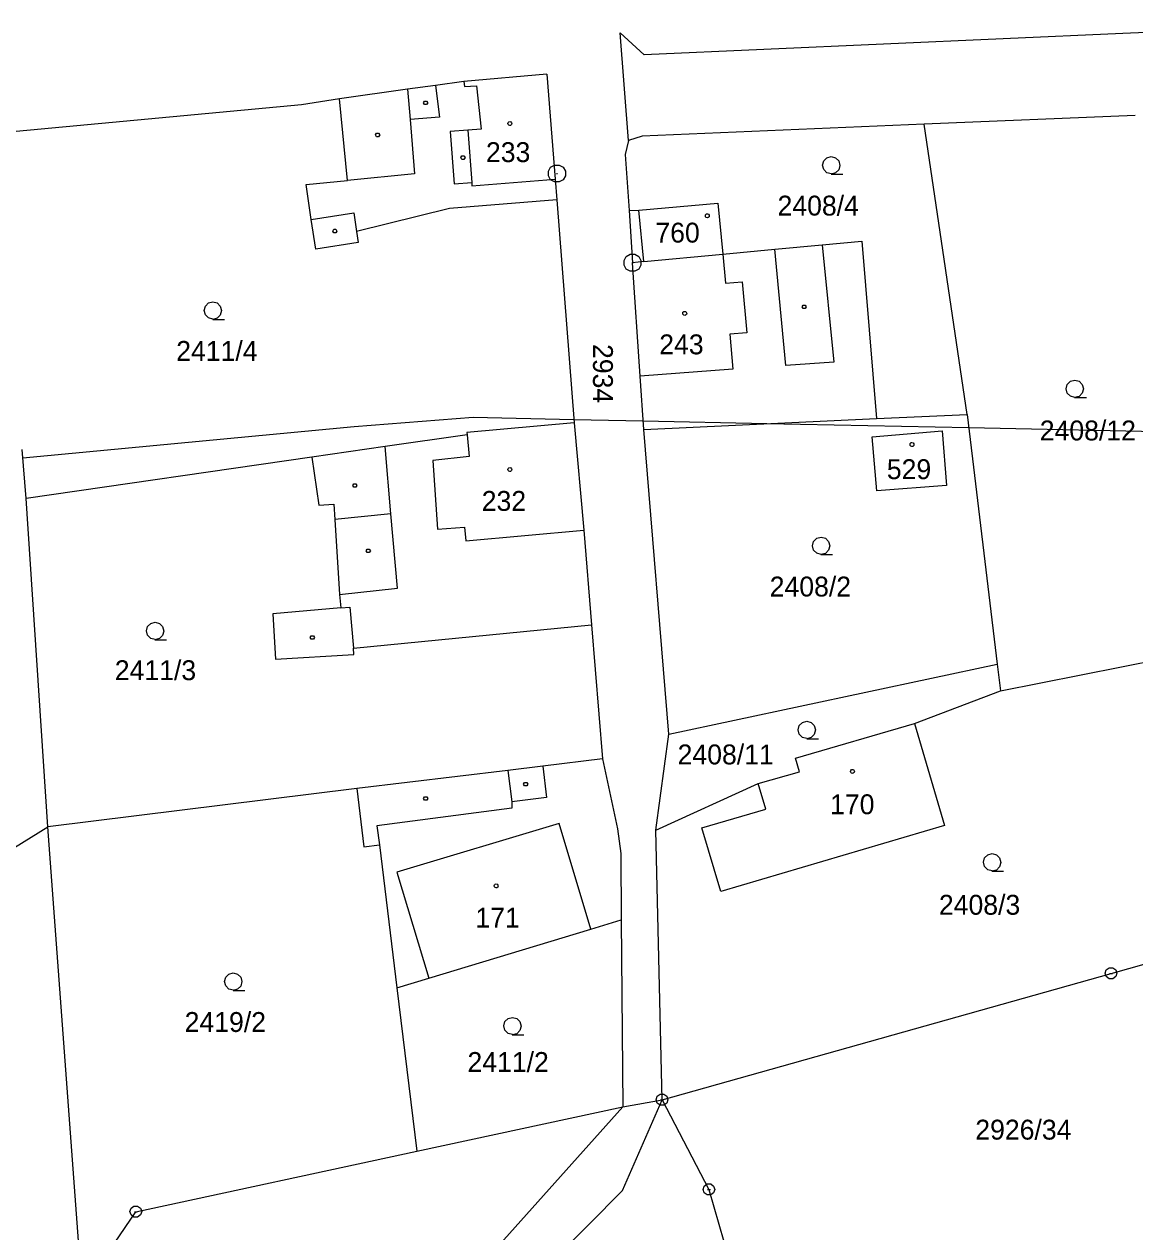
# Model space of a CAD drawing. Extents: x -760611 to -758411, y -1176479 to -1174807.
# Drawn here: x -758977.4 to -758882.5, y -1175044.9 to -1174941.6 of the extents above; entities that cross this region are included whole.
import ezdxf

# ---------------------------------------------------------------- set-up
doc = ezdxf.new("R2010")
doc.units = 0
for name, color, linetype in [('1', 7, 'Continuous'), ('11', 7, 'Continuous'), ('12', 7, 'Continuous'), ('2', 7, 'Continuous'), ('3', 7, 'Continuous'), ('4', 7, 'Continuous'), ('5', 7, 'Continuous'), ('8', 7, 'Continuous')]:
    doc.layers.add(name, color=color, linetype=linetype)

msp = doc.modelspace()

# ---------------------------------------------------------------- linework, layer by layer
at = {"layer": '1'}
for p, q in [((-758866.53, -1174941.63), (-758883.52, -1174942.43)), ((-758924.41, -1174944.26), (-758926.48, -1174942.38)), ((-758925.76, -1174951.58), (-758926.48, -1174942.38)), ((-758883.52, -1174942.43), (-758924.41, -1174944.26)), ((-758932.75, -1174945.91), (-758939.82, -1174946.52)), ((-758932.75, -1174945.91), (-758932.02, -1174954.88)), ((-758944.64, -1174947.2), (-758950.45, -1174948.02)), ((-758942.24, -1174946.86), (-758944.64, -1174947.2)), ((-758939.82, -1174946.52), (-758942.24, -1174946.86)), ((-758953.71, -1174948.54), (-758979.01, -1174950.9)), ((-758950.45, -1174948.02), (-758953.71, -1174948.54)), ((-758949.77, -1174954.98), (-758950.45, -1174948.02)), ((-758882.46, -1174949.43), (-758900.48, -1174950.19)), ((-758900.48, -1174950.19), (-758924.59, -1174951.2)), ((-758896.81, -1174974.98), (-758900.48, -1174950.19)), ((-758925.76, -1174951.58), (-758926.04, -1174952.76)), ((-758924.59, -1174951.2), (-758925.76, -1174951.58)), ((-758926.04, -1174952.76), (-758925.71, -1174957.56)), ((-758953.31, -1174955.33), (-758949.77, -1174954.98)), ((-758952.88, -1174958.34), (-758953.31, -1174955.33)), ((-758932.02, -1174954.88), (-758931.88, -1174956.64)), ((-758931.88, -1174956.64), (-758941.05, -1174957.38)), ((-758931.88, -1174956.64), (-758930.4, -1174975.71)), ((-758941.05, -1174957.38), (-758948.99, -1174959.36)), ((-758925.71, -1174957.56), (-758924.87, -1174957.52)), ((-758925.71, -1174957.56), (-758925.41, -1174962.02)), ((-758924.87, -1174957.52), (-758918.11, -1174956.92)), ((-758918.11, -1174956.92), (-758917.69, -1174961.29)), ((-758952.49, -1174960.85), (-758952.88, -1174958.34)), ((-758948.99, -1174959.36), (-758948.85, -1174960.3)), ((-758948.85, -1174960.3), (-758952.49, -1174960.85)), ((-758917.69, -1174961.29), (-758913.24, -1174960.87)), ((-758913.24, -1174960.87), (-758909.2, -1174960.49)), ((-758909.2, -1174960.49), (-758905.83, -1174960.17)), ((-758905.83, -1174960.17), (-758904.56, -1174975.34)), ((-758924.46, -1174961.93), (-758925.41, -1174962.02)), ((-758924.46, -1174961.93), (-758917.69, -1174961.29)), ((-758924.75, -1174971.71), (-758925.41, -1174962.02)), ((-758924.44, -1174976.28), (-758924.75, -1174971.71)), ((-758924.44, -1174976.28), (-758904.56, -1174975.34)), ((-758904.56, -1174975.34), (-758896.81, -1174974.98)), ((-758896.81, -1174974.98), (-758894.24, -1174996.33)), ((-758930.4, -1174975.71), (-758939.56, -1174976.54)), ((-758930.4, -1174975.71), (-758929.57, -1174984.88)), ((-758922.31, -1175002.32), (-758924.44, -1174976.28)), ((-758904.93, -1174976.9), (-758898.96, -1174976.4)), ((-758898.96, -1174976.4), (-758898.57, -1174981.06)), ((-758939.55, -1174976.72), (-758946.56, -1174977.73)), ((-758939.56, -1174976.54), (-758939.55, -1174976.72)), ((-758904.54, -1174981.52), (-758904.93, -1174976.9)), ((-758977.24, -1174982.16), (-758977.57, -1174977.98)), ((-758946.56, -1174977.73), (-758952.83, -1174978.64)), ((-758952.83, -1174978.64), (-758977.24, -1174982.16)), ((-758952.83, -1174978.64), (-758952.23, -1174982.73)), ((-758898.57, -1174981.06), (-758904.54, -1174981.52)), ((-758975.38, -1175010.24), (-758977.24, -1174982.16)), ((-758952.23, -1174982.73), (-758950.94, -1174982.65)), ((-758950.94, -1174982.65), (-758950.86, -1174983.96)), ((-758950.86, -1174983.96), (-758950.45, -1174990.37)), ((-758929.57, -1174984.88), (-758928.91, -1174992.96)), ((-758950.45, -1174990.37), (-758950.34, -1174991.53)), ((-758950.34, -1174991.53), (-758956.16, -1174992.02)), ((-758956.16, -1174992.02), (-758955.92, -1174995.9)), ((-758949.27, -1174994.98), (-758928.91, -1174992.96)), ((-758928.91, -1174992.96), (-758927.98, -1175004.43)), ((-758949.23, -1174995.52), (-758949.27, -1174994.98)), ((-758893.97, -1174998.61), (-758874.82, -1174994.83)), ((-758955.92, -1174995.9), (-758949.23, -1174995.52)), ((-758922.31, -1175002.32), (-758894.24, -1174996.33)), ((-758894.24, -1174996.33), (-758893.97, -1174998.61)), ((-758901.31, -1175001.41), (-758893.97, -1174998.61)), ((-758911.49, -1175004.38), (-758901.31, -1175001.41)), ((-758901.31, -1175001.41), (-758898.74, -1175010.13)), ((-758923.43, -1175010.52), (-758922.31, -1175002.32)), ((-758933.09, -1175005.05), (-758936.07, -1175005.41)), ((-758927.98, -1175004.43), (-758933.09, -1175005.05)), ((-758927.98, -1175004.43), (-758926.69, -1175010.42)), ((-758911.15, -1175005.53), (-758911.49, -1175004.38)), ((-758936.07, -1175005.41), (-758948.97, -1175006.97)), ((-758914.69, -1175006.52), (-758911.15, -1175005.53)), ((-758948.97, -1175006.97), (-758975.38, -1175010.24)), ((-758948.97, -1175006.97), (-758948.37, -1175011.95)), ((-758923.43, -1175010.52), (-758914.69, -1175006.52)), ((-758914.01, -1175008.73), (-758914.69, -1175006.52)), ((-758919.48, -1175010.33), (-758914.01, -1175008.73)), ((-758993.13, -1175021.18), (-758975.38, -1175010.24)), ((-758972.45, -1175049.88), (-758975.38, -1175010.24)), ((-758926.69, -1175010.42), (-758926.42, -1175012.52)), ((-758917.87, -1175015.77), (-758919.48, -1175010.33)), ((-758898.74, -1175010.13), (-758917.87, -1175015.77)), ((-758922.89, -1175033.57), (-758923.43, -1175010.52)), ((-758948.37, -1175011.95), (-758947.05, -1175011.78)), ((-758947.05, -1175011.78), (-758945.55, -1175023.99)), ((-758926.42, -1175012.52), (-758926.37, -1175018.18)), ((-758928.99, -1175018.97), (-758926.37, -1175018.18)), ((-758926.37, -1175018.18), (-758926.24, -1175034.18)), ((-758942.83, -1175023.17), (-758928.99, -1175018.97)), ((-758884.52, -1175022.76), (-758870.77, -1175018.87)), ((-758922.89, -1175033.57), (-758884.52, -1175022.76)), ((-758945.55, -1175023.99), (-758942.83, -1175023.17)), ((-758945.55, -1175023.99), (-758943.84, -1175037.97)), ((-758943.98, -1175053.98), (-758926.24, -1175034.18)), ((-758943.84, -1175037.97), (-758926.24, -1175034.18)), ((-758926.26, -1175041.33), (-758922.89, -1175033.57)), ((-758926.24, -1175034.18), (-758922.89, -1175033.57)), ((-758922.89, -1175033.57), (-758918.88, -1175041.24)), ((-758967.86, -1175043.13), (-758943.84, -1175037.97)), ((-758940.47, -1175055.61), (-758926.26, -1175041.33)), ((-758918.88, -1175041.24), (-758914.91, -1175055.04)), ((-758972.45, -1175049.88), (-758967.86, -1175043.13))]:
    msp.add_line(p, q, dxfattribs=at)
at = {"layer": '11'}
msp.add_lwpolyline([(-758806.29, -1174972.54), (-758816.73, -1174973.48), (-758837.26, -1174975.35), (-758844.54, -1174975.48), (-758845.16, -1174975.49), (-758847.76, -1174975.54), (-758855.49, -1174975.68), (-758858.89, -1174976.93), (-758860.9, -1174976.89), (-758870.73, -1174976.68), (-758875.96, -1174976.57), (-758877.9, -1174976.53), (-758896.67, -1174976.14), (-758913.93, -1174975.78), (-758924.49, -1174975.56), (-758930.42, -1174975.44), (-758939.02, -1174975.26), (-758949.2, -1174976.06), (-758977.51, -1174978.74)], dxfattribs=at)
at = {"layer": '12'}
for p, q in [((-758932.75, -1174945.91), (-758939.82, -1174946.52)), ((-758932.75, -1174945.91), (-758932.02, -1174954.88)), ((-758939.82, -1174946.52), (-758939.78, -1174946.97)), ((-758939.78, -1174946.97), (-758938.74, -1174946.89)), ((-758938.74, -1174946.89), (-758938.36, -1174950.61)), ((-758938.36, -1174950.61), (-758939.5, -1174950.7)), ((-758939.5, -1174950.7), (-758939.16, -1174955.16)), ((-758939.16, -1174955.16), (-758939.14, -1174955.46)), ((-758939.14, -1174955.46), (-758932.02, -1174954.88)), ((-758924.87, -1174957.52), (-758918.11, -1174956.92)), ((-758924.46, -1174961.93), (-758924.87, -1174957.52)), ((-758918.11, -1174956.92), (-758917.69, -1174961.29)), ((-758924.46, -1174961.93), (-758925.41, -1174962.02)), ((-758924.46, -1174961.93), (-758917.69, -1174961.29)), ((-758924.46, -1174961.93), (-758917.69, -1174961.29)), ((-758917.69, -1174961.29), (-758917.47, -1174963.78)), ((-758924.75, -1174971.71), (-758925.41, -1174962.02)), ((-758917.47, -1174963.78), (-758916.03, -1174963.66)), ((-758916.03, -1174963.66), (-758915.65, -1174968.02)), ((-758915.65, -1174968.02), (-758917.1, -1174968.14)), ((-758917.1, -1174968.14), (-758916.84, -1174971.13)), ((-758916.84, -1174971.13), (-758924.75, -1174971.71)), ((-758930.4, -1174975.71), (-758939.56, -1174976.54)), ((-758930.4, -1174975.71), (-758929.57, -1174984.88)), ((-758904.93, -1174976.9), (-758898.96, -1174976.4)), ((-758898.96, -1174976.4), (-758898.57, -1174981.06)), ((-758939.56, -1174976.54), (-758939.55, -1174976.72)), ((-758939.55, -1174976.72), (-758939.38, -1174978.58)), ((-758904.54, -1174981.52), (-758904.93, -1174976.9)), ((-758939.38, -1174978.58), (-758942.48, -1174978.93)), ((-758942.48, -1174978.93), (-758942.08, -1174984.79)), ((-758898.57, -1174981.06), (-758904.54, -1174981.52)), ((-758942.08, -1174984.79), (-758939.76, -1174984.62)), ((-758939.76, -1174984.62), (-758939.65, -1174985.78)), ((-758939.65, -1174985.78), (-758929.57, -1174984.88)), ((-758911.49, -1175004.38), (-758901.31, -1175001.41)), ((-758901.31, -1175001.41), (-758898.74, -1175010.13)), ((-758911.15, -1175005.53), (-758911.49, -1175004.38)), ((-758914.69, -1175006.52), (-758911.15, -1175005.53)), ((-758914.01, -1175008.73), (-758914.69, -1175006.52)), ((-758919.48, -1175010.33), (-758914.01, -1175008.73)), ((-758931.69, -1175009.94), (-758945.56, -1175014.12)), ((-758928.99, -1175018.97), (-758931.69, -1175009.94)), ((-758917.87, -1175015.77), (-758919.48, -1175010.33)), ((-758898.74, -1175010.13), (-758917.87, -1175015.77)), ((-758945.56, -1175014.12), (-758942.83, -1175023.17)), ((-758942.83, -1175023.17), (-758928.99, -1175018.97))]:
    msp.add_line(p, q, dxfattribs=at)
at = {"layer": '3'}
for points in [[(-758908.42, -1174954.43), (-758908.8, -1174954.33), (-758909.07, -1174954.06), (-758909.17, -1174953.69), (-758909.07, -1174953.32), (-758908.8, -1174953.05), (-758908.43, -1174952.95), (-758908.06, -1174953.05), (-758907.79, -1174953.32), (-758907.69, -1174953.7), (-758907.79, -1174954.08), (-758908.06, -1174954.35), (-758908.44, -1174954.45), (-758907.44, -1174954.45)], [(-758961.27, -1174966.84), (-758961.65, -1174966.74), (-758961.92, -1174966.47), (-758962.02, -1174966.1), (-758961.92, -1174965.73), (-758961.65, -1174965.46), (-758961.28, -1174965.36), (-758960.91, -1174965.46), (-758960.64, -1174965.73), (-758960.54, -1174966.11), (-758960.64, -1174966.49), (-758960.91, -1174966.76), (-758961.29, -1174966.86), (-758960.29, -1174966.86)], [(-758887.61, -1174973.53), (-758887.99, -1174973.43), (-758888.26, -1174973.16), (-758888.36, -1174972.79), (-758888.26, -1174972.42), (-758887.99, -1174972.15), (-758887.62, -1174972.05), (-758887.25, -1174972.15), (-758886.98, -1174972.42), (-758886.88, -1174972.8), (-758886.98, -1174973.18), (-758887.25, -1174973.45), (-758887.63, -1174973.55), (-758886.63, -1174973.55)], [(-758909.29, -1174986.95), (-758909.67, -1174986.85), (-758909.94, -1174986.58), (-758910.04, -1174986.21), (-758909.94, -1174985.84), (-758909.67, -1174985.57), (-758909.3, -1174985.47), (-758908.93, -1174985.57), (-758908.66, -1174985.84), (-758908.56, -1174986.22), (-758908.66, -1174986.6), (-758908.93, -1174986.87), (-758909.31, -1174986.97), (-758908.31, -1174986.97)], [(-758966.21, -1174994.23), (-758966.59, -1174994.13), (-758966.86, -1174993.86), (-758966.96, -1174993.49), (-758966.86, -1174993.12), (-758966.59, -1174992.85), (-758966.22, -1174992.75), (-758965.85, -1174992.85), (-758965.58, -1174993.12), (-758965.48, -1174993.5), (-758965.58, -1174993.88), (-758965.85, -1174994.15), (-758966.23, -1174994.25), (-758965.23, -1174994.25)], [(-758910.51, -1175002.69), (-758910.89, -1175002.59), (-758911.16, -1175002.32), (-758911.26, -1175001.95), (-758911.16, -1175001.58), (-758910.89, -1175001.31), (-758910.52, -1175001.21), (-758910.15, -1175001.31), (-758909.88, -1175001.58), (-758909.78, -1175001.96), (-758909.88, -1175002.34), (-758910.15, -1175002.61), (-758910.53, -1175002.71), (-758909.53, -1175002.71)], [(-758894.68, -1175014.01), (-758895.06, -1175013.91), (-758895.33, -1175013.64), (-758895.43, -1175013.27), (-758895.33, -1175012.9), (-758895.06, -1175012.63), (-758894.69, -1175012.53), (-758894.32, -1175012.63), (-758894.05, -1175012.9), (-758893.95, -1175013.28), (-758894.05, -1175013.66), (-758894.32, -1175013.93), (-758894.7, -1175014.03), (-758893.7, -1175014.03)], [(-758959.52, -1175024.2), (-758959.9, -1175024.1), (-758960.17, -1175023.83), (-758960.27, -1175023.46), (-758960.17, -1175023.09), (-758959.9, -1175022.82), (-758959.53, -1175022.72), (-758959.16, -1175022.82), (-758958.89, -1175023.09), (-758958.79, -1175023.47), (-758958.89, -1175023.85), (-758959.16, -1175024.12), (-758959.54, -1175024.22), (-758958.54, -1175024.22)], [(-758935.67, -1175028), (-758936.05, -1175027.9), (-758936.32, -1175027.63), (-758936.42, -1175027.26), (-758936.32, -1175026.89), (-758936.05, -1175026.62), (-758935.68, -1175026.52), (-758935.31, -1175026.62), (-758935.04, -1175026.89), (-758934.94, -1175027.27), (-758935.04, -1175027.65), (-758935.31, -1175027.92), (-758935.69, -1175028.02), (-758934.69, -1175028.02)]]:
    msp.add_lwpolyline(points, dxfattribs=at)
at = {"layer": '4'}
for p, q in [((-758944.64, -1174947.2), (-758944.43, -1174949.78)), ((-758942.24, -1174946.86), (-758941.91, -1174949.57)), ((-758939.82, -1174946.52), (-758939.78, -1174946.97)), ((-758939.78, -1174946.97), (-758938.74, -1174946.89)), ((-758938.74, -1174946.89), (-758938.36, -1174950.61)), ((-758941.91, -1174949.57), (-758944.43, -1174949.78)), ((-758944.43, -1174949.78), (-758944.04, -1174954.42)), ((-758938.36, -1174950.61), (-758939.5, -1174950.7)), ((-758939.5, -1174950.7), (-758940.99, -1174950.81)), ((-758940.99, -1174950.81), (-758940.65, -1174955.27)), ((-758939.5, -1174950.7), (-758939.16, -1174955.16)), ((-758944.04, -1174954.42), (-758949.77, -1174954.98)), ((-758940.65, -1174955.27), (-758939.16, -1174955.16)), ((-758939.16, -1174955.16), (-758939.14, -1174955.46)), ((-758939.14, -1174955.46), (-758932.02, -1174954.88)), ((-758952.88, -1174958.34), (-758949.24, -1174957.76)), ((-758949.24, -1174957.76), (-758948.99, -1174959.36)), ((-758924.46, -1174961.93), (-758924.87, -1174957.52)), ((-758912.31, -1174970.81), (-758913.24, -1174960.87)), ((-758909.2, -1174960.49), (-758908.21, -1174970.51)), ((-758917.69, -1174961.29), (-758917.47, -1174963.78)), ((-758917.47, -1174963.78), (-758916.03, -1174963.66)), ((-758916.03, -1174963.66), (-758915.65, -1174968.02)), ((-758915.65, -1174968.02), (-758917.1, -1174968.14)), ((-758917.1, -1174968.14), (-758916.84, -1174971.13)), ((-758916.84, -1174971.13), (-758924.75, -1174971.71)), ((-758908.21, -1174970.51), (-758912.31, -1174970.81)), ((-758939.55, -1174976.72), (-758939.38, -1174978.58)), ((-758946.06, -1174983.49), (-758946.56, -1174977.73)), ((-758939.38, -1174978.58), (-758942.48, -1174978.93)), ((-758942.48, -1174978.93), (-758942.08, -1174984.79)), ((-758946.06, -1174983.49), (-758950.86, -1174983.96)), ((-758945.5, -1174989.83), (-758946.06, -1174983.49)), ((-758942.08, -1174984.79), (-758939.76, -1174984.62)), ((-758939.76, -1174984.62), (-758939.65, -1174985.78)), ((-758939.65, -1174985.78), (-758929.57, -1174984.88)), ((-758950.45, -1174990.37), (-758945.5, -1174989.83)), ((-758950.34, -1174991.53), (-758949.57, -1174991.46)), ((-758949.57, -1174991.46), (-758949.27, -1174994.98)), ((-758933.09, -1175005.05), (-758932.77, -1175007.73)), ((-758936.07, -1175005.41), (-758935.74, -1175008.09)), ((-758932.77, -1175007.73), (-758935.74, -1175008.09)), ((-758935.74, -1175008.09), (-758935.72, -1175008.64)), ((-758935.72, -1175008.64), (-758947.27, -1175010.16)), ((-758947.27, -1175010.16), (-758947.05, -1175011.78)), ((-758931.69, -1175009.94), (-758945.56, -1175014.12)), ((-758928.99, -1175018.97), (-758931.69, -1175009.94)), ((-758945.56, -1175014.12), (-758942.83, -1175023.17))]:
    msp.add_line(p, q, dxfattribs=at)
at = {"layer": '5'}
for points in [[(-758943.01, -1174948.21), (-758942.92, -1174948.36), (-758943.01, -1174948.51), (-758943.19, -1174948.51), (-758943.28, -1174948.36), (-758943.19, -1174948.21)], [(-758935.9, -1174949.96), (-758935.8, -1174949.98), (-758935.75, -1174950.07), (-758935.73, -1174950.13), (-758935.75, -1174950.22), (-758935.83, -1174950.29), (-758935.9, -1174950.3), (-758935.99, -1174950.27), (-758936.05, -1174950.21), (-758936.07, -1174950.13), (-758936.05, -1174950.04), (-758935.97, -1174949.97)], [(-758947.11, -1174950.95), (-758947.02, -1174951.1), (-758947.11, -1174951.25), (-758947.29, -1174951.25), (-758947.38, -1174951.1), (-758947.29, -1174950.95)], [(-758939.82, -1174952.89), (-758939.73, -1174953.04), (-758939.82, -1174953.19), (-758940, -1174953.19), (-758940.09, -1174953.04), (-758940, -1174952.89)], [(-758919.02, -1174957.84), (-758918.92, -1174957.86), (-758918.87, -1174957.95), (-758918.85, -1174958.01), (-758918.87, -1174958.1), (-758918.95, -1174958.17), (-758919.02, -1174958.18), (-758919.11, -1174958.15), (-758919.17, -1174958.09), (-758919.19, -1174958.01), (-758919.17, -1174957.92), (-758919.09, -1174957.85)], [(-758950.76, -1174959.16), (-758950.67, -1174959.31), (-758950.76, -1174959.46), (-758950.94, -1174959.46), (-758951.03, -1174959.31), (-758950.94, -1174959.16)], [(-758910.65, -1174965.64), (-758910.56, -1174965.79), (-758910.65, -1174965.94), (-758910.83, -1174965.94), (-758910.92, -1174965.79), (-758910.83, -1174965.64)], [(-758920.95, -1174966.18), (-758920.85, -1174966.2), (-758920.8, -1174966.29), (-758920.78, -1174966.35), (-758920.8, -1174966.44), (-758920.88, -1174966.51), (-758920.95, -1174966.52), (-758921.04, -1174966.49), (-758921.1, -1174966.43), (-758921.12, -1174966.35), (-758921.1, -1174966.26), (-758921.02, -1174966.19)], [(-758901.53, -1174977.39), (-758901.43, -1174977.41), (-758901.38, -1174977.5), (-758901.36, -1174977.56), (-758901.38, -1174977.65), (-758901.46, -1174977.72), (-758901.53, -1174977.73), (-758901.62, -1174977.7), (-758901.68, -1174977.64), (-758901.7, -1174977.56), (-758901.68, -1174977.47), (-758901.6, -1174977.4)], [(-758935.9, -1174979.53), (-758935.8, -1174979.55), (-758935.75, -1174979.64), (-758935.73, -1174979.7), (-758935.75, -1174979.79), (-758935.83, -1174979.86), (-758935.9, -1174979.87), (-758935.99, -1174979.84), (-758936.05, -1174979.78), (-758936.07, -1174979.7), (-758936.05, -1174979.61), (-758935.97, -1174979.54)], [(-758949.05, -1174980.91), (-758948.96, -1174981.06), (-758949.05, -1174981.21), (-758949.23, -1174981.21), (-758949.32, -1174981.06), (-758949.23, -1174980.91)], [(-758947.91, -1174986.5), (-758947.82, -1174986.65), (-758947.91, -1174986.8), (-758948.09, -1174986.8), (-758948.18, -1174986.65), (-758948.09, -1174986.5)], [(-758952.69, -1174993.91), (-758952.6, -1174994.06), (-758952.69, -1174994.21), (-758952.87, -1174994.21), (-758952.96, -1174994.06), (-758952.87, -1174993.91)], [(-758906.62, -1175005.33), (-758906.52, -1175005.35), (-758906.47, -1175005.44), (-758906.45, -1175005.5), (-758906.47, -1175005.59), (-758906.55, -1175005.66), (-758906.62, -1175005.67), (-758906.71, -1175005.64), (-758906.77, -1175005.58), (-758906.79, -1175005.5), (-758906.77, -1175005.41), (-758906.69, -1175005.34)], [(-758934.46, -1175006.44), (-758934.37, -1175006.59), (-758934.46, -1175006.74), (-758934.64, -1175006.74), (-758934.73, -1175006.59), (-758934.64, -1175006.44)], [(-758943, -1175007.66), (-758942.91, -1175007.81), (-758943, -1175007.96), (-758943.18, -1175007.96), (-758943.27, -1175007.81), (-758943.18, -1175007.66)], [(-758937.07, -1175015.12), (-758936.97, -1175015.14), (-758936.92, -1175015.23), (-758936.9, -1175015.29), (-758936.92, -1175015.38), (-758937, -1175015.45), (-758937.07, -1175015.46), (-758937.16, -1175015.43), (-758937.22, -1175015.37), (-758937.24, -1175015.29), (-758937.22, -1175015.2), (-758937.14, -1175015.13)]]:
    msp.add_lwpolyline(points, close=True, dxfattribs=at)
at = {"layer": '8'}
for p, q in [((-758931.92, -1174954.39), (-758931.82, -1174954.39)), ((-758925.46, -1174962.02), (-758925.36, -1174962.02)), ((-758884.64, -1175022.76), (-758884.4, -1175022.76)), ((-758923.01, -1175033.57), (-758922.77, -1175033.57)), ((-758919, -1175041.24), (-758918.76, -1175041.24)), ((-758967.98, -1175043.13), (-758967.74, -1175043.13))]:
    msp.add_line(p, q, dxfattribs=at)
for points in [[(-758931.68, -1174953.67), (-758931.34, -1174953.86), (-758931.15, -1174954.2), (-758931.15, -1174954.59), (-758931.34, -1174954.93), (-758931.68, -1174955.12), (-758932.07, -1174955.12), (-758932.41, -1174954.93), (-758932.6, -1174954.59), (-758932.6, -1174954.2), (-758932.41, -1174953.86), (-758932.07, -1174953.67)], [(-758925.22, -1174961.3), (-758924.88, -1174961.49), (-758924.69, -1174961.83), (-758924.69, -1174962.22), (-758924.88, -1174962.56), (-758925.22, -1174962.75), (-758925.61, -1174962.75), (-758925.95, -1174962.56), (-758926.14, -1174962.22), (-758926.14, -1174961.83), (-758925.95, -1174961.49), (-758925.61, -1174961.3)], [(-758884.37, -1175022.28), (-758884.12, -1175022.46), (-758884.02, -1175022.75), (-758884.12, -1175023.04), (-758884.37, -1175023.22), (-758884.68, -1175023.22), (-758884.93, -1175023.04), (-758885.03, -1175022.75), (-758884.93, -1175022.46), (-758884.68, -1175022.28)], [(-758922.74, -1175033.09), (-758922.49, -1175033.27), (-758922.39, -1175033.56), (-758922.49, -1175033.85), (-758922.74, -1175034.03), (-758923.05, -1175034.03), (-758923.3, -1175033.85), (-758923.4, -1175033.56), (-758923.3, -1175033.27), (-758923.05, -1175033.09)], [(-758918.73, -1175040.76), (-758918.48, -1175040.94), (-758918.38, -1175041.23), (-758918.48, -1175041.52), (-758918.73, -1175041.7), (-758919.04, -1175041.7), (-758919.29, -1175041.52), (-758919.39, -1175041.23), (-758919.29, -1175040.94), (-758919.04, -1175040.76)], [(-758967.71, -1175042.65), (-758967.46, -1175042.83), (-758967.36, -1175043.12), (-758967.46, -1175043.41), (-758967.71, -1175043.59), (-758968.02, -1175043.59), (-758968.27, -1175043.41), (-758968.37, -1175043.12), (-758968.27, -1175042.83), (-758968.02, -1175042.65)]]:
    msp.add_lwpolyline(points, close=True, dxfattribs=at)

# ---------------------------------------------------------------- texts
at = {"layer": '2'}
for s, p in [('233', (-758937.94, -1174953.42)), ('2408/4', (-758913.02, -1174957.99)), ('760', (-758923.46, -1174960.3)), ('243', (-758923.13, -1174969.85)), ('2411/4', (-758964.41, -1174970.41)), ('2408/12', (-758890.61, -1174977.21)), ('529', (-758903.68, -1174980.52)), ('232', (-758938.3, -1174983.23)), ('2408/2', (-758913.69, -1174990.55)), ('2411/3', (-758969.66, -1174997.7)), ('2408/11', (-758921.56, -1175004.9)), ('170', (-758908.53, -1175009.16)), ('2408/3', (-758899.23, -1175017.75)), ('171', (-758938.84, -1175018.85)), ('2419/2', (-758963.69, -1175027.77)), ('2411/2', (-758939.52, -1175031.19)), ('2926/34', (-758896.12, -1175036.97))]:
    msp.add_text(s, height=1.7, dxfattribs=at).set_placement(p)
msp.add_text('2934', height=1.7, rotation=269.9777, dxfattribs=at).set_placement((-758928.79, -1174968.97))

doc.saveas('drawing.dxf')
